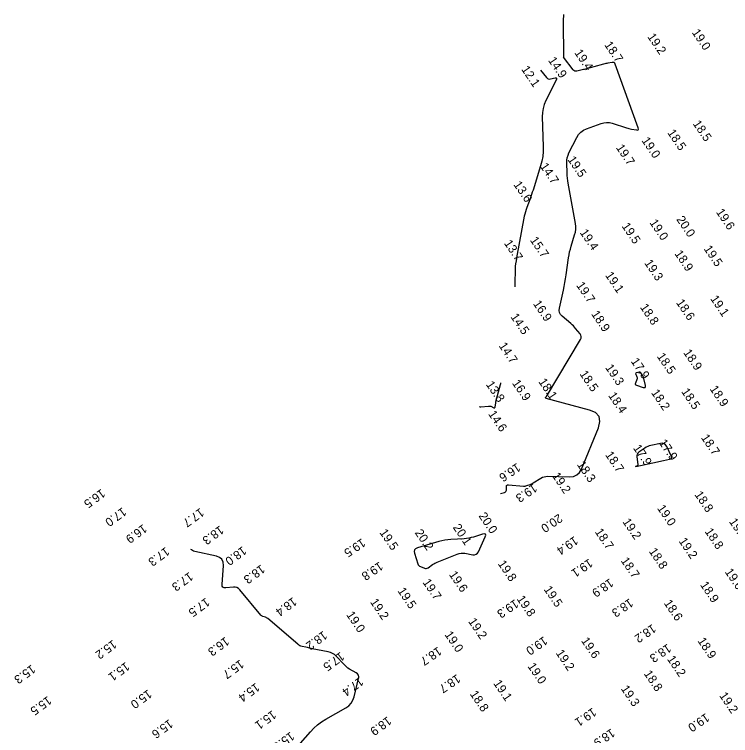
# Model space of a CAD drawing. Extents: x 824616 to 827440, y 158441 to 163197.
# Drawn here: x 826192.8 to 826605.2, y 159814.3 to 160229.3 of the extents above; entities that cross this region are included whole.
import ezdxf

# ---------------------------------------------------------------- set-up
doc = ezdxf.new("R2010")
doc.units = 0
for name, color, linetype in [('V-CHAN-CONT-EL14', 7, 'Continuous'), ('V-CHAN-CONT-EL18', 7, 'Continuous'), ('V-CHAN-CONT-EL20', 7, 'Continuous'), ('V-TOPO-SOUN', 7, 'Continuous')]:
    doc.layers.add(name, color=color, linetype=linetype)

msp = doc.modelspace()

# ---------------------------------------------------------------- linework, layer by layer
at = {"layer": 'V-CHAN-CONT-EL14'}
for points in [[(826495.77, 160197.26), (826499.28, 160192.95), (826499.74, 160192.5), (826500.26, 160192.22), (826500.84, 160192.11), (826501.48, 160192.16), (826504.16, 160192.72), (826504.7, 160192.76), (826505.01, 160192.62), (826505.07, 160192.29), (826504.88, 160191.77), (826498.85, 160179.71), (826497.89, 160177.47), (826497.23, 160175.16), (826496.87, 160172.78), (826496.8, 160170.34), (826497.34, 160153.29), (826497.32, 160150.44), (826497.05, 160147.62), (826496.55, 160144.84), (826495.81, 160142.09), (826491.45, 160128.19), (826491.04, 160126.93), (826490.62, 160125.68), (826490.18, 160124.43), (826489.72, 160123.19), (826487.85, 160118.23), (826487.42, 160116.98), (826487.03, 160115.72), (826486.71, 160114.44), (826486.44, 160113.15), (826482.03, 160089.26), (826481.94, 160088.82), (826481.86, 160088.38), (826481.78, 160087.94), (826481.69, 160087.5), (826481.35, 160085.73), (826481.28, 160085.29), (826481.22, 160084.85), (826481.19, 160084.4), (826481.17, 160083.95), (826481.02, 160072.98), (826480.98, 160072.63), (826480.97, 160072.58)], [(826460.65, 160003.65), (826460.9, 160003.51), (826461.5, 160003.5), (826465.9, 160003.86), (826466.02, 160003.87), (826466.13, 160003.87), (826466.24, 160003.88), (826466.36, 160003.88), (826466.81, 160003.88), (826466.92, 160003.87), (826467.03, 160003.86), (826467.14, 160003.82), (826467.24, 160003.78), (826468.91, 160002.92), (826469.19, 160002.82), (826469.4, 160002.85), (826469.55, 160003.01), (826469.64, 160003.29), (826470, 160005.84), (826470.09, 160006.38), (826470.19, 160006.91), (826470.31, 160007.44), (826470.45, 160007.97), (826472.79, 160016.4), (826472.95, 160017), (826472.97, 160017.21)]]:
    msp.add_lwpolyline(points, dxfattribs=at)
at = {"layer": 'V-CHAN-CONT-EL18'}
for points in [[(826509.01, 160229.28), (826508.83, 160225.55), (826508.91, 160204.6)], [(826472.72, 159953.57), (826475.06, 159954.26), (826475.5, 159954.46), (826475.83, 159954.75), (826476.03, 159955.14), (826476.11, 159955.61), (826476.19, 159957.72), (826476.27, 159958.17), (826476.48, 159958.48), (826476.81, 159958.65), (826477.27, 159958.67), (826485.93, 159957.88), (826486.42, 159957.86), (826486.9, 159957.89), (826487.38, 159957.99), (826487.85, 159958.13), (826489.72, 159958.83), (826490.18, 159959.01), (826490.63, 159959.22), (826491.07, 159959.45), (826491.5, 159959.7), (826495.96, 159962.45), (826496.87, 159962.93), (826497.81, 159963.26), (826498.79, 159963.45), (826499.81, 159963.5), (826512.54, 159963.23), (826514.81, 159963.47), (826516.71, 159964.29), (826518.22, 159965.7), (826519.35, 159967.69), (826529.07, 159991.36), (826529.99, 159995.01), (826529.45, 159997.93), (826527.46, 160000.13), (826524.01, 160001.62), (826499.12, 160008.34), (826499.04, 160008.37), (826498.97, 160008.4), (826498.91, 160008.44), (826498.85, 160008.49), (826498.62, 160008.71), (826498.58, 160008.77), (826498.56, 160008.82), (826498.58, 160008.87), (826498.63, 160008.92), (826499.18, 160009.34), (826499.19, 160009.35), (826499.2, 160009.36), (826499.2, 160009.37), (826499.21, 160009.38), (826499.22, 160009.43), (826499.22, 160009.44), (826499.23, 160009.45), (826499.23, 160009.47), (826499.24, 160009.48), (826518.76, 160042.23), (826519.13, 160043.07), (826519.21, 160043.89), (826519, 160044.69), (826518.52, 160045.47), (826516.01, 160048.53), (826515.36, 160049.28), (826514.69, 160050.01), (826513.98, 160050.7), (826513.25, 160051.36), (826508.26, 160055.65), (826507.36, 160056.63), (826506.79, 160057.74), (826506.58, 160058.96), (826506.71, 160060.29), (826508.95, 160070.61), (826509.4, 160072.8), (826509.81, 160074.99), (826510.19, 160077.18), (826510.52, 160079.39), (826511.93, 160089.27), (826512.2, 160090.95), (826512.54, 160092.61), (826512.94, 160094.26), (826513.41, 160095.89), (826515.43, 160102.39), (826515.83, 160104.02), (826516.03, 160105.67), (826516.04, 160107.32), (826515.84, 160108.99), (826511.74, 160132.15), (826511.51, 160133.61), (826511.33, 160135.08), (826511.2, 160136.55), (826511.13, 160138.03), (826510.94, 160143.96), (826510.98, 160145.42), (826511.2, 160146.85), (826511.6, 160148.23), (826512.17, 160149.58), (826516.59, 160158.41), (826517.63, 160160.1), (826518.93, 160161.51), (826520.48, 160162.64), (826522.28, 160163.48), (826530.68, 160166.54), (826532.27, 160166.98), (826533.86, 160167.15), (826535.45, 160167.04), (826537.05, 160166.66), (826545.25, 160164.02), (826545.96, 160163.8), (826546.67, 160163.61), (826547.39, 160163.45), (826548.12, 160163.31), (826551.03, 160162.81), (826551.64, 160162.78), (826552, 160162.96), (826552.12, 160163.35), (826551.99, 160163.95), (826538.77, 160200.7), (826538.51, 160201.21), (826538.14, 160201.55), (826537.66, 160201.7), (826537.09, 160201.68), (826534.58, 160201.25), (826533.95, 160201.14), (826533.33, 160201.01), (826532.71, 160200.86), (826532.1, 160200.7), (826520.81, 160197.6), (826520.75, 160197.59), (826520.69, 160197.57), (826520.63, 160197.56), (826520.57, 160197.54), (826516.75, 160196.67), (826516.12, 160196.61), (826515.55, 160196.71), (826515.04, 160196.99), (826514.59, 160197.43), (826508.91, 160204.6)], [(826353.31, 159805.13), (826363.26, 159816.5), (826365.25, 159818.6), (826367.4, 159820.51), (826369.71, 159822.23), (826372.17, 159823.76), (826383.6, 159830.23), (826385.32, 159831.43), (826386.71, 159832.9), (826387.75, 159834.62), (826388.44, 159836.61), (826391.06, 159847.17), (826391.17, 159848.17), (826390.98, 159849.05), (826390.48, 159849.79), (826389.67, 159850.41), (826385.85, 159852.6), (826384.92, 159853.19), (826384.04, 159853.83), (826383.21, 159854.55), (826382.44, 159855.32), (826378.19, 159859.94), (826377.18, 159860.88), (826376.06, 159861.63), (826374.84, 159862.19), (826373.5, 159862.55), (826364.32, 159864.31), (826363.62, 159864.45), (826362.91, 159864.6), (826362.21, 159864.75), (826361.51, 159864.91), (826357.64, 159865.83), (826357.48, 159865.87), (826357.33, 159865.94), (826357.18, 159866.01), (826357.05, 159866.11), (826356.52, 159866.51), (826356.39, 159866.62), (826356.26, 159866.72), (826356.13, 159866.83), (826356, 159866.93), (826338.68, 159881.63), (826338.38, 159881.86), (826338.06, 159882.06), (826337.72, 159882.23), (826337.37, 159882.37), (826335.92, 159882.86), (826335.57, 159883), (826335.25, 159883.19), (826334.96, 159883.42), (826334.7, 159883.69), (826322.57, 159898.23), (826321.81, 159898.96), (826320.95, 159899.45), (826319.99, 159899.7), (826318.93, 159899.71), (826314.52, 159899.25), (826313.56, 159899.29), (826312.9, 159899.63), (826312.53, 159900.28), (826312.45, 159901.24), (826313.16, 159912.22), (826313.01, 159914.2), (826312.29, 159915.76), (826311, 159916.88), (826309.13, 159917.57), (826296.67, 159920.31), (826295.97, 159920.51), (826295.33, 159920.82), (826294.74, 159921.21), (826294.48, 159921.45)]]:
    msp.add_lwpolyline(points, dxfattribs=at)
for points in [[(826551.42, 160019.92), (826551.38, 160019.55), (826551.27, 160019.18), (826550.42, 160017.16), (826550.31, 160016.74), (826550.36, 160016.4), (826550.59, 160016.13), (826550.98, 160015.94), (826554.96, 160014.67), (826555.63, 160014.55), (826556.06, 160014.7), (826556.25, 160015.11), (826556.19, 160015.79), (826555.32, 160019.8), (826555.2, 160020.22), (826555.06, 160020.63), (826554.87, 160021.03), (826554.65, 160021.41), (826553.62, 160023.02), (826553.4, 160023.28), (826553.14, 160023.44), (826552.84, 160023.5), (826552.5, 160023.45), (826551.07, 160023.08), (826550.77, 160022.96), (826550.6, 160022.78), (826550.55, 160022.53), (826550.63, 160022.22), (826551.27, 160020.66), (826551.39, 160020.29)], [(826551.78, 159969.89), (826551.66, 159969.73), (826551.48, 159969.6), (826550.62, 159969.17), (826550.47, 159969.08), (826550.42, 159969.03), (826550.49, 159969.02), (826550.66, 159969.06), (826563.05, 159971.89), (826563.92, 159972.08), (826564.8, 159972.28), (826565.67, 159972.46), (826566.55, 159972.65), (826570.05, 159973.36), (826570.76, 159973.62), (826571.16, 159974.04), (826571.25, 159974.6), (826571.01, 159975.33), (826568.41, 159980.68), (826567.77, 159981.64), (826566.96, 159982.26), (826565.98, 159982.53), (826564.83, 159982.44), (826559.32, 159981.31), (826558.38, 159981.07), (826557.48, 159980.73), (826556.63, 159980.3), (826555.81, 159979.78), (826552.39, 159977.31), (826551.82, 159976.79), (826551.44, 159976.18), (826551.26, 159975.49), (826551.27, 159974.71), (826551.84, 159970.3), (826551.84, 159970.08)]]:
    msp.add_lwpolyline(points, close=True, dxfattribs=at)
at = {"layer": 'V-CHAN-CONT-EL20'}
msp.add_lwpolyline([(826440.67, 159926.81), (826438.97, 159926.46), (826437.3, 159926.02), (826424.86, 159922.34), (826423.85, 159921.87), (826423.24, 159921.2), (826423.02, 159920.31), (826423.19, 159919.22), (826425.06, 159913.2), (826425.29, 159912.65), (826425.62, 159912.2), (826426.05, 159911.83), (826426.58, 159911.55), (826428.9, 159910.63), (826429.47, 159910.47), (826430.02, 159910.46), (826430.56, 159910.6), (826431.08, 159910.88), (826433.65, 159912.7), (826434.26, 159913.1), (826434.89, 159913.47), (826435.54, 159913.8), (826436.21, 159914.09), (826447.87, 159918.76), (826448.94, 159919.11), (826450.03, 159919.3), (826451.14, 159919.33), (826452.25, 159919.21), (826456.76, 159918.41), (826457.81, 159918.36), (826458.7, 159918.63), (826459.42, 159919.2), (826459.98, 159920.09), (826463.92, 159928.59), (826464.26, 159929.64), (826464.13, 159930.26), (826463.53, 159930.47), (826462.45, 159930.26), (826457.18, 159928.58), (826455.85, 159928.21), (826454.51, 159927.92), (826453.15, 159927.72), (826451.78, 159927.6), (826444.11, 159927.19), (826442.38, 159927.05)], close=True, dxfattribs=at)

# ---------------------------------------------------------------- texts
at = {"layer": 'V-TOPO-SOUN'}
for s, rotation, p in [('19.2 ', 304.2, (826557.09, 160216.46)), ('19.0 ', 304.2, (826582.7, 160218.89)), ('18.7 ', 304.2, (826532.29, 160211.78)), ('19.4 ', 304.2, (826515.06, 160207.21)), ('14.9 ', 304.2, (826499.94, 160202.85)), ('12.1 ', 304.2, (826484.48, 160197.72)), ('18.5 ', 304.2, (826583.25, 160166.43)), ('18.5 ', 304.2, (826568.61, 160161.2)), ('19.0 ', 304.2, (826553.75, 160156.73)), ('19.7 ', 304.2, (826539.01, 160152.6)), ('19.5 ', 304.2, (826511.12, 160145.77)), ('14.7 ', 304.2, (826495.27, 160141.86)), ('13.6 ', 304.2, (826479.99, 160131.4)), ('20.0 ', 304.2, (826573.78, 160111.35)), ('19.6 ', 304.2, (826596.63, 160115.54)), ('19.5 ', 304.2, (826542.31, 160107.46)), ('19.0 ', 304.2, (826558.33, 160109.47)), ('19.4 ', 304.2, (826518.18, 160103.78)), ('15.7 ', 304.2, (826489.5, 160099.39)), ('13.7 ', 304.2, (826474.55, 160097.59)), ('18.9 ', 304.2, (826572.69, 160091.65)), ('19.5 ', 304.2, (826589.57, 160094.42)), ('19.3 ', 304.2, (826555.35, 160086.25)), ('19.1 ', 304.2, (826532.78, 160079.2)), ('19.7 ', 304.2, (826516.15, 160073.41)), ('16.9 ', 304.2, (826491.26, 160062.83)), ('18.6 ', 304.2, (826573.62, 160063.48)), ('19.1 ', 304.2, (826593.34, 160065.68)), ('18.8 ', 304.2, (826552.85, 160060.79)), ('14.5 ', 304.2, (826478.29, 160055.29)), ('18.9 ', 304.2, (826524.77, 160056.86)), ('14.7 ', 304.2, (826471.51, 160038.6)), ('18.9 ', 304.2, (826577.79, 160034.67)), ('17.9 ', 304.2, (826547.57, 160029.66)), ('18.5 ', 304.2, (826562.57, 160032.55)), ('19.3 ', 304.2, (826532.85, 160026.02)), ('18.5 ', 304.2, (826518.06, 160022.43)), ('13.8 ', 304.2, (826464.13, 160016.35)), ('16.9 ', 304.2, (826479.17, 160017.12)), ('18.1 ', 304.2, (826494.39, 160017.89)), ('18.5 ', 304.2, (826576.61, 160012.25)), ('18.9 ', 304.2, (826593.01, 160013.8)), ('18.4 ', 304.2, (826534.55, 160009.97)), ('18.2 ', 304.2, (826559.28, 160011.62)), ('14.6 ', 304.2, (826465.44, 159999.36)), ('17.9 ', 304.2, (826563.7, 159982.84)), ('18.7 ', 304.2, (826587.98, 159985.75)), ('17.9 ', 304.2, (826548.85, 159979.79)), ('18.7 ', 304.2, (826532.79, 159975.88)), ('16.6 ', 214.2, (826482.15, 159971.4)), ('18.3 ', 304.2, (826516.54, 159970.25)), ('19.2 ', 304.2, (826502.22, 159963.76)), ('16.5 ', 216.2, (826242.85, 159956.51)), ('19.3 ', 214.2, (826491.74, 159959.53)), ('18.8 ', 304.2, (826584.23, 159953.02)), ('17.0 ', 216.2, (826255.07, 159945.91)), ('17.7 ', 216.2, (826299.81, 159945.54)), ('19.0 ', 304.2, (826562.72, 159945.16)), ('20.0 ', 304.2, (826459.9, 159940.74)), ('20.0 ', 214.2, (826506.29, 159942.15)), ('19.2 ', 304.2, (826542.77, 159937.35)), ('19.2 ', 304.2, (826604.11, 159937.44)), ('16.9 ', 216.2, (826266.93, 159936.2)), ('18.3 ', 216.2, (826311.13, 159935.42)), ('20.1 ', 304.2, (826445.09, 159934.11)), ('19.5 ', 304.2, (826402.84, 159931.18)), ('20.2 ', 304.2, (826423.17, 159931.07)), ('18.7 ', 304.2, (826526.87, 159931.55)), ('18.8 ', 304.2, (826590.12, 159931.74)), ('19.5 ', 214.2, (826392.86, 159928.04)), ('19.4 ', 214.2, (826515.3, 159929.28)), ('19.2 ', 304.2, (826575.14, 159926.22)), ('17.3 ', 216.2, (826279.91, 159923.07)), ('18.0 ', 216.2, (826324.22, 159923.5)), ('18.8 ', 304.2, (826557.95, 159920.33)), ('19.8 ', 214.2, (826403.01, 159914.62)), ('19.8 ', 304.2, (826471, 159913.21)), ('19.1 ', 214.2, (826523.75, 159916.37)), ('18.7 ', 304.3, (826541.78, 159914.98)), ('18.3 ', 216.2, (826334.85, 159912.94)), ('19.6 ', 304.2, (826601.68, 159908.53)), ('17.3 ', 216.2, (826293.49, 159908.67)), ('19.6 ', 304.2, (826442.87, 159907.02)), ('19.7 ', 304.2, (826427.67, 159902.51)), ('18.9 ', 214.2, (826535.65, 159904.99)), ('18.9 ', 304.2, (826587.46, 159901.02)), ('19.5 ', 304.2, (826413.26, 159897.55)), ('19.5 ', 304.2, (826497.42, 159898.46)), ('17.5 ', 216.2, (826303.08, 159893.88)), ('18.4 ', 216.2, (826353.22, 159894.22)), ('19.8 ', 304.2, (826481.87, 159892.95)), ('19.2 ', 304.2, (826397.43, 159891.19)), ('19.3 ', 214.2, (826481, 159892.97)), ('18.3 ', 214.2, (826547.04, 159893.48)), ('18.6 ', 304.2, (826566.59, 159890.52)), ('19.0 ', 304.2, (826383.73, 159883.83)), ('19.2 ', 304.2, (826453.94, 159880)), ('18.2 ', 214.2, (826560.19, 159878.7)), ('18.2 ', 216.2, (826370.68, 159874.81)), ('19.0 ', 304.2, (826440.31, 159872.43)), ('15.2 ', 216.2, (826249.49, 159869.63)), ('16.3 ', 216.2, (826314.27, 159871.38)), ('19.0 ', 214.2, (826497.66, 159871.66)), ('19.6 ', 304.2, (826518.94, 159868.9)), ('18.9 ', 304.2, (826586, 159868.78)), ('18.7 ', 214.2, (826436.78, 159865.7)), ('18.3 ', 214.2, (826568.9, 159867.35)), ('17.5 ', 216.2, (826380.6, 159862.7)), ('19.2 ', 304.2, (826504.36, 159861.81)), ('18.2 ', 304.2, (826568.43, 159858.37)), ('15.1 ', 216.2, (826256.91, 159856.89)), ('15.7 ', 216.2, (826322.76, 159858.27)), ('19.0 ', 304.2, (826488.11, 159854.19)), ('15.3 ', 216.2, (826202.7, 159855.37)), ('17.4 ', 216.2, (826391.56, 159848.18)), ('18.7 ', 214.2, (826447.57, 159849.85)), ('18.8 ', 304.2, (826555.05, 159849.95)), ('15.4 ', 216.2, (826331.82, 159844.9)), ('19.1 ', 304.2, (826468.4, 159844.38)), ('15.0 ', 216.2, (826269.73, 159841.07)), ('18.8 ', 304.2, (826454.89, 159838.21)), ('19.3 ', 304.2, (826541.84, 159841.28)), ('15.5 ', 216.2, (826211.99, 159837.3)), ('19.2 ', 304.2, (826598.49, 159837.31)), ('15.1 ', 216.2, (826341.34, 159829.09)), ('19.1 ', 214.2, (826525.8, 159830.58)), ('19.0 ', 214.2, (826590.95, 159827.46)), ('15.6 ', 216.2, (826281.92, 159823.96)), ('18.9 ', 216.2, (826407.68, 159825.6)), ('15.6 ', 216.2, (826351.82, 159816.76)), ('18.9 ', 214.2, (826536.52, 159818.62))]:
    msp.add_text(s, height=5, rotation=rotation, dxfattribs=at).set_placement(p)

doc.saveas('drawing.dxf')
